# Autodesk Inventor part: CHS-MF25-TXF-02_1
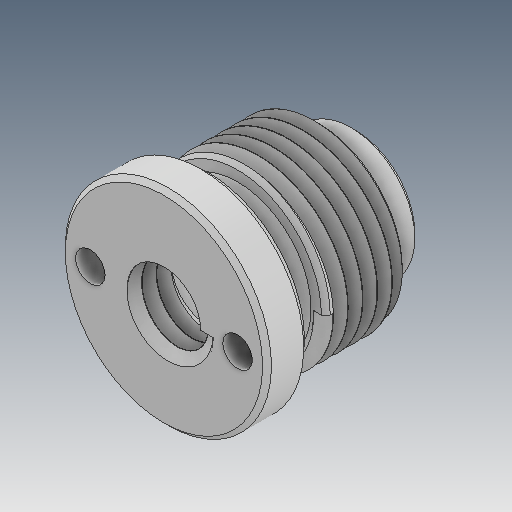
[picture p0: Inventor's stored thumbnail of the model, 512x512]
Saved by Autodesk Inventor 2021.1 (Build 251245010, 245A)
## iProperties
Created: 2019-04
Part Number: CHS-MF25-TXF-02_1
Material: Ogólny
Document SubType Name: Modeling
Designer: user
Density: 1 g/cm^3
Appearance: Domyślna
Author: user
Revision Number: ÈÎºÎ
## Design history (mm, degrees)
feature "ÊäÈë1"
node "Bryła1"
